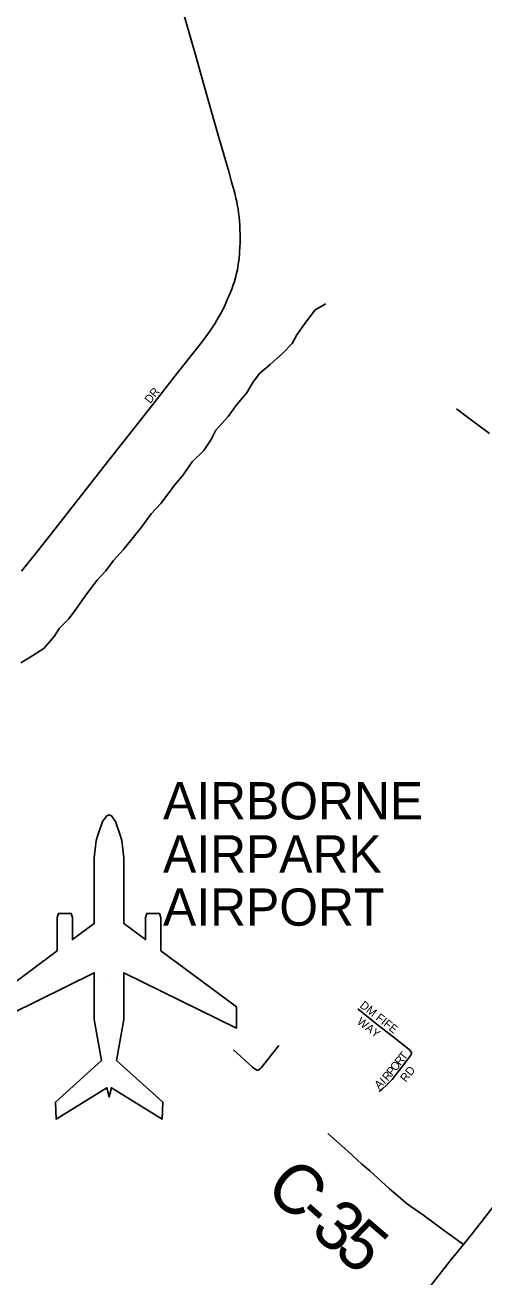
# Model space of a CAD drawing. Extents: x 1442749 to 1756758, y 235267 to 677782.
# Drawn here: x 1603104 to 1605877, y 522575 to 530141 of the extents above; entities that cross this region are included whole.
import ezdxf

# ---------------------------------------------------------------- set-up
doc = ezdxf.new("R2010")
doc.units = 0
for name, color, linetype in [('GM_X_Airport_Class_2', 7, 'Continuous'), ('GM_X_Airport_Location_Class_2', 7, 'Continuous'), ('GM_X_Airport_Text_Class_2', 7, 'Continuous'), ('GM_X_City_Street', 7, 'Continuous'), ('GM_X_City_Street_Text', 7, 'Continuous'), ('GM_X_County_Road', 7, 'Continuous'), ('GM_X_County_Road_Text', 7, 'Continuous'), ('GM_X_Minor_River', 7, 'Continuous')]:
    doc.layers.add(name, color=color, linetype=linetype)

msp = doc.modelspace()

# ---------------------------------------------------------------- linework, layer by layer
at = {"layer": 'GM_X_Airport_Class_2'}
msp.add_lwpolyline([(1602842.3, 524079.3), (1603521.3, 524414), (1603521.3, 524132.2), (1603566.3, 523882.8), (1603286.9, 523632.2), (1603291.3, 523529), (1603597.4, 523718.6), (1603611.5, 523663.1), (1603625.6, 523718.6), (1603931.6, 523529), (1603936, 523632.2), (1603656.6, 523882.8), (1603701.7, 524132.2), (1603701.7, 524414), (1604380.7, 524079.3), (1604380.7, 524208.8), (1603924.3, 524546.3), (1603924.3, 524747.8), (1603917.2, 524772.3), (1603839.5, 524772.3), (1603832.4, 524747.8), (1603832.4, 524614.3), (1603701.7, 524710.9), (1603701.7, 524710.9), (1603701.7, 525108.8), (1603688.5, 525214), (1603677.6, 525251.5), (1603650.6, 525328.1), (1603625.7, 525362.2), (1603611.5, 525368.1), (1603597.3, 525362.2), (1603572.4, 525328.1), (1603545.4, 525251.5), (1603534.4, 525214), (1603521.3, 525108.8), (1603521.3, 524710.9), (1603390.6, 524614.3), (1603390.6, 524747.8), (1603383.5, 524772.3), (1603305.8, 524772.3), (1603298.7, 524747.8), (1603298.7, 524546.3), (1602842.3, 524208.8)], dxfattribs=at)
at = {"layer": 'GM_X_Airport_Location_Class_2'}
msp.add_line((1603611.5, 524385.5), (1603611.5, 524385.5), dxfattribs=at)
at = {"layer": 'GM_X_City_Street'}
for points in [[(1604275.1, 529462.3), (1604235.3, 529602.6), (1604187.1, 529772.8), (1604133.1, 529961.9), (1604077.4, 530157.4), (1604028.1, 530330.8), (1603968.8, 530538.9), (1603921.7, 530706.1), (1603867.8, 530895.2), (1603819.1, 531068.8), (1603779.9, 531213.5), (1603741.1, 531356.6), (1603728.9, 531403.4)], [(1604369, 528592.1), (1604375.2, 528613.6), (1604380.3, 528632.7), (1604383.7, 528647.1), (1604386.9, 528662.4), (1604390.2, 528680.3), (1604392.5, 528696), (1604395.4, 528716.8), (1604397.2, 528735.1), (1604399, 528753.6), (1604400.2, 528769.8), (1604401.9, 528799.1), (1604402.9, 528826.8), (1604403.4, 528850.8), (1604403.5, 528876.4), (1604402.8, 528903.7), (1604401.7, 528929.7), (1604399.7, 528956.6), (1604397.4, 528981.4), (1604394.4, 529005.9), (1604390.9, 529030), (1604386.6, 529055), (1604383.1, 529074.7), (1604378.5, 529093.9), (1604373.1, 529116.8), (1604367.1, 529138.7), (1604351.9, 529194.3), (1604334.9, 529256.1), (1604275.1, 529462.3)], [(1603083.3, 526840), (1603173.4, 526952.8), (1603264.4, 527069.2), (1603604.3, 527502.9), (1603875.8, 527848.7), (1604023.4, 528037.2), (1604150.1, 528196.4), (1604196.2, 528256.5), (1604221.1, 528291.6), (1604250, 528335.9), (1604263.4, 528357.1), (1604277, 528381.4), (1604288.1, 528401.4), (1604298.8, 528422.3), (1604310.3, 528445.2), (1604320.1, 528467.2), (1604330.3, 528489.9), (1604338.8, 528510.7), (1604346.9, 528530.9), (1604354.7, 528550.5), (1604361.9, 528570.6), (1604369, 528592.1)], [(1605114, 524195.6), (1605221, 524108.6), (1605327.7, 524026), (1605425.1, 523949.1), (1605436.1, 523938.1), (1605438, 523935), (1605439, 523930.4), (1605439, 523927.1)], [(1604363.2, 523948.8), (1604479.3, 523843.2), (1604494.6, 523830.6), (1604501.8, 523826.7), (1604506.9, 523825.6), (1604511.4, 523825.6), (1604515.9, 523827.4)], [(1604515.9, 523827.4), (1604519.4, 523828.8), (1604524.3, 523832.2), (1604530.5, 523838.9), (1604637, 523975.1)], [(1605244.5, 523695.7), (1605266.8, 523714.7), (1605286.8, 523731.9), (1605305.2, 523750.2), (1605322.5, 523769.5), (1605362.6, 523821.3), (1605405.3, 523875.8), (1605434.3, 523915.5), (1605437.2, 523920.2), (1605438.6, 523923.7), (1605439, 523927.1)]]:
    msp.add_lwpolyline(points, dxfattribs=at)
at = {"layer": 'GM_X_County_Road'}
for points in [[(1605752.9, 522772.1), (1605801.3, 522832), (1605861.7, 522909.4), (1606051, 523155.1), (1606217.4, 523374.6), (1606452, 523676.2)], [(1605752.9, 522772.1), (1605695.5, 522813.6), (1605639.3, 522854.1), (1605569, 522907.5), (1605550.6, 522921.5), (1605530.7, 522935.1), (1605511.9, 522948), (1605494.1, 522960.1), (1605473.4, 522974), (1605436.1, 523000.5), (1605405.5, 523024), (1605358.9, 523062.9), (1605306.9, 523108.5), (1605186.9, 523216.1), (1605140, 523257.3), (1605054.9, 523334.6), (1604932.7, 523441.4)], [(1604893.1, 521678.7), (1604943, 521742.6), (1605073.1, 521911.4), (1605208.5, 522080.3), (1605340.4, 522247.6), (1605671.6, 522671.3), (1605752.9, 522772.1)]]:
    msp.add_lwpolyline(points, dxfattribs=at)
at = {"layer": 'GM_X_Minor_River'}
for points in [[(1603078.2, 526286.9), (1603150.9, 526330.3), (1603217.5, 526373.6), (1603280.5, 526445.1), (1603311.2, 526496.9), (1603367.9, 526552.5), (1603408.7, 526606.2), (1603451.5, 526667.9), (1603494.3, 526725.5), (1603539.1, 526787.2), (1603591.8, 526842.8), (1603638.7, 526904.4), (1603699.6, 526971.9), (1603764.7, 527053.5), (1603807.4, 527107.1), (1603866.5, 527186.7), (1603925.3, 527250.2), (1603968.1, 527307.9), (1604006.8, 527359.6), (1604055.6, 527417.2), (1604114.7, 527500.8), (1604183.6, 527570.3), (1604228.5, 527635.9), (1604257.2, 527693.8), (1604330.4, 527775.2), (1604383.3, 527848.8), (1604442.3, 527916.4), (1604481.1, 527980.1), (1604519.8, 528035.8), (1604584.6, 528089.3), (1604663.6, 528160.6), (1604718.4, 528216.1), (1604747, 528268), (1604800.1, 528345.6), (1604857, 528419.2), (1604921.6, 528456.5)], [(1605711.8, 527821.6), (1605777.4, 527770.7), (1605848.9, 527719.7), (1605910.5, 527672.8)]]:
    msp.add_lwpolyline(points, dxfattribs=at)

# ---------------------------------------------------------------- texts
at = {"layer": 'GM_X_Airport_Text_Class_2'}
for s, p in [('AIRBORNE', (1603937.9, 525340.7)), ('AIRPARK', (1603937.9, 525019.5)), ('AIRPORT', (1603937.9, 524698.2))]:
    msp.add_text(s, height=225, rotation=0.00001, dxfattribs=at).set_placement(p)
at = {"layer": 'GM_X_City_Street_Text'}
for s, rotation, p in [('DR', 51.33663, (1603860.2, 527850.2)), ('DM FIFE', 321.84508, (1605122.9, 524208.6)), ('WAY', 322.42654, (1605105.6, 524109.7)), ('T', 51.35358, (1605396.6, 523880.2)), ('O', 51.36194, (1605344.4, 523815)), ('R', 51.3326, (1605371.8, 523849.3)), ('R', 48.98517, (1605294.9, 523755.9)), ('P', 51.28282, (1605322.3, 523787.5)), ('RD', 51.33663, (1605405, 523749.1)), ('A', 42.88233, (1605242.8, 523706.5)), ('I', 43.94152, (1605275.8, 523737.1))]:
    msp.add_text(s, height=50, rotation=rotation, dxfattribs=at).set_placement(p)
at = {"layer": 'GM_X_County_Road_Text'}
for s, rotation, p in [('C', 318.3911, (1604542.5, 523093.5)), ('3', 318.6094, (1604819.9, 522847.4)), ('-', 318.44548, (1604727, 522929.7)), ('5', 319.36071, (1604961.8, 522722.4))]:
    msp.add_text(s, height=300, rotation=rotation, dxfattribs=at).set_placement(p)

doc.saveas('drawing.dxf')
